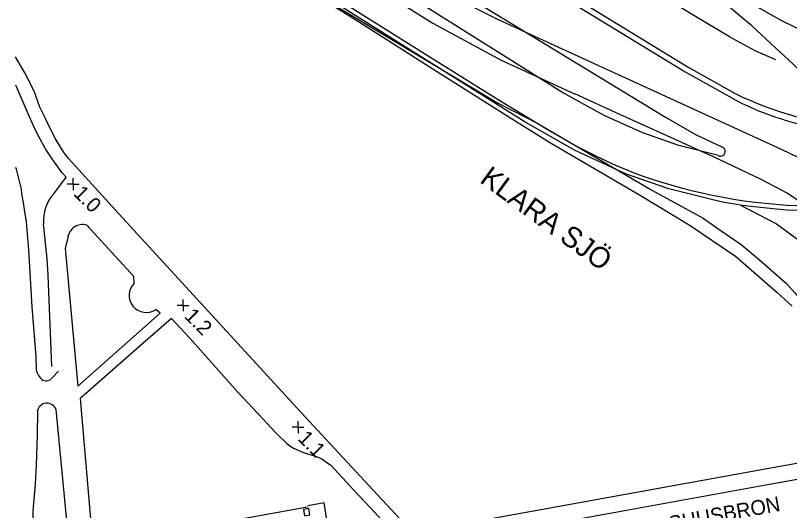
# Model space of a CAD drawing. Extents: x 1596643 to 1597288, y 13057194 to 13057957.
# Drawn here: x 1596648.4 to 1596778.7, y 13057439.2 to 13057522.5 of the extents above; entities that cross this region are included whole.
import ezdxf

# ---------------------------------------------------------------- set-up
doc = ezdxf.new("R2010")
doc.units = 0
for name, color, linetype in [('A spårmitt L', 7, 'Continuous'), ('BAS bro ej def L', 7, 'Continuous'), ('BAS fastighetsgräns samfällighet L', 7, 'Continuous'), ('BAS gång- cykelväg L', 7, 'Continuous'), ('BAS kajkant L', 7, 'Continuous'), ('BAS Level 16', 7, 'Continuous'), ('BAS Level 18', 7, 'Continuous'), ('BAS Level 19', 7, 'Continuous'), ('BAS Level 34', 7, 'Continuous'), ('BAS markytetext T', 7, 'Continuous'), ('BAS väg T', 7, 'Continuous'), ('BAS vägbanekant L', 7, 'Continuous'), ('BAS vägbanekant skymd L', 7, 'Continuous')]:
    doc.layers.add(name, color=color, linetype=linetype)

msp = doc.modelspace()

# ---------------------------------------------------------------- linework, layer by layer
at = {"layer": 'A spårmitt L'}
msp.add_arc((1597114.01, 13057796.63), 410, 212.1854, 226.2937, dxfattribs=at)
at = {"layer": 'BAS bro ej def L'}
for points in [[(1596776.38, 13057515.07), (1596772.93, 13057516.59), (1596768.6, 13057518.91), (1596762.32, 13057522.67), (1596686.06, 13057569.11), (1596672.38, 13057577.4), (1596669.04, 13057579.43), (1596663.37, 13057582.83)], [(1596675.99, 13057583.08), (1596765.97, 13057528.32), (1596771.95, 13057524.7), (1596777.33, 13057521.65), (1596783.79, 13057518.55), (1596789.25, 13057516.42), (1596794.25, 13057515.28), (1596798.61, 13057515.01), (1596803.07, 13057515.31)], [(1596766.73, 13057498.92), (1596760.08, 13057500.64), (1596754.02, 13057502.74), (1596747.52, 13057505.66), (1596740.35, 13057509.61), (1596648.37, 13057567.37)], [(1596765.57, 13057491.51), (1596758.36, 13057493.35), (1596751.1, 13057495.85), (1596742.51, 13057499.82), (1596734.05, 13057504.69), (1596648.37, 13057558.52)], [(1596670.44, 13057558.6), (1596757.81, 13057505.41), (1596763.01, 13057502.44), (1596767.29, 13057500.38)], [(1596873.3, 13057525.88), (1596855.75, 13057517.01), (1596837.58, 13057507.61), (1596820.66, 13057499.01), (1596812.84, 13057495.44), (1596806.32, 13057492.94), (1596797.79, 13057490.83), (1596791.9, 13057490.12), (1596786.01, 13057489.63), (1596782.53, 13057489.62), (1596780.07, 13057489.65), (1596778.3, 13057489.75), (1596776.53, 13057489.91), (1596771.66, 13057490.41), (1596770.47, 13057490.58)], [(1596770.47, 13057490.58), (1596768.82, 13057490.83), (1596767.72, 13057491.04), (1596765.57, 13057491.51)], [(1596701.55, 13057432.92), (1596795.38, 13057449.95), (1596800, 13057453.76)]]:
    msp.add_lwpolyline(points, dxfattribs=at)
msp.add_arc((1596767.1, 13057499.62), 0.789, 240.3812, 77.7075, dxfattribs=at)
at = {"layer": 'BAS fastighetsgräns samfällighet L'}
msp.add_lwpolyline([(1596648.37, 13057557.67), (1596669.21, 13057544.62), (1596696.73, 13057527.52), (1596729.51, 13057507.81), (1596732.16, 13057506.46), (1596736.21, 13057504.41), (1596755.64, 13057493.06), (1596764.14, 13057488.41), (1596767.22, 13057486.28), (1596770.57, 13057483.95), (1596773.67, 13057481.35), (1596776.84, 13057478.59), (1596778.22, 13057477.39), (1596779.59, 13057475.84), (1596783.22, 13057471.46), (1596786.31, 13057467.11), (1596788.64, 13057463.85), (1596790.09, 13057461.2), (1596791.17, 13057459.15)], dxfattribs=at)
at = {"layer": 'BAS gång- cykelväg L'}
for points in [[(1596654.84, 13057492.51), (1596656.89, 13057495.29), (1596656.18, 13057496.08), (1596654.54, 13057498.39), (1596653.4, 13057500.08), (1596652.26, 13057502.21), (1596651.49, 13057503.81), (1596650.5, 13057505.95), (1596648.43, 13057510.76)], [(1596648.37, 13057496.96), (1596648.47, 13057496.66), (1596648.79, 13057495.51), (1596649.01, 13057494.63), (1596649.32, 13057493.29), (1596649.41, 13057492.47), (1596649.67, 13057491.03), (1596649.84, 13057489.86), (1596650.17, 13057487.77), (1596650.55, 13057483.06), (1596651.13, 13057473.46), (1596651.78, 13057465.08), (1596651.87, 13057462.85)], [(1596654.49, 13057463.43), (1596653.9, 13057478.77), (1596653.68, 13057481.54), (1596653.1, 13057487.43)], [(1596668.37, 13057477.42), (1596668.3, 13057478.55), (1596660.37, 13057487.21)], [(1596657.17, 13057485.05), (1596656.75, 13057483.32), (1596658.88, 13057460.07)], [(1596658.88, 13057460.07), (1596672.71, 13057472.36), (1596671.98, 13057472.98)], [(1596685.78, 13057459.15), (1596677.72, 13057468.15), (1596674.62, 13057471.47), (1596669.81, 13057467.28), (1596660.57, 13057459.15)], [(1596654.59, 13057461.55), (1596655.62, 13057462.6)], [(1596660.57, 13057459.15), (1596659.29, 13057457.99), (1596661.01, 13057437.74)], [(1596685.78, 13057459.15), (1596689.24, 13057455.42), (1596692.23, 13057452.24), (1596694.09, 13057450.42), (1596694.74, 13057449.91), (1596695.2, 13057449.63), (1596696.08, 13057449.26), (1596696.88, 13057448.94), (1596698.08, 13057448.55), (1596698.88, 13057448.29), (1596699.97, 13057447.87), (1596701.53, 13057446.75), (1596705.35, 13057442.6), (1596708.96, 13057438.78), (1596712.4, 13057434.89)], [(1596657.09, 13057436.87), (1596655.2, 13057456.14)]]:
    msp.add_lwpolyline(points, dxfattribs=at)
for centre, radius, start, end in [((1596659.69, 13057488), 6.62, 137.1066, 184.924), ((1596659.7, 13057484.76), 2.55, 74.737, 173.4662), ((1596670.38, 13057475.37), 2.87, 134.4079, 303.9057), ((1596654.59, 13057463.38), 2.77, 190.9855, 234.6811), ((1596653.52, 13057462.33), 1.33, 246.1732, 323.6558), ((1596653.66, 13057455.59), 1.64, 19.44, 169.7795)]:
    msp.add_arc(centre, radius, start, end, dxfattribs=at)
at = {"layer": 'BAS kajkant L'}
for points in [[(1596648.37, 13057557.76), (1596661.05, 13057549.78), (1596672.77, 13057542.39), (1596688.02, 13057532.81), (1596705.04, 13057522.16), (1596719.86, 13057512.73), (1596731.89, 13057505.16), (1596738.44, 13057501.07), (1596745.06, 13057497.19), (1596753.44, 13057492.3), (1596761.8, 13057487.28), (1596769.62, 13057482.01), (1596776.64, 13057475.89), (1596777.87, 13057474.75), (1596779.15, 13057473.58)], [(1596693.3, 13057459.15), (1596665.79, 13057489.11), (1596657.34, 13057498.35), (1596656.59, 13057499.36), (1596656.08, 13057500.15), (1596655.1, 13057501.76), (1596654.26, 13057503.36), (1596653.39, 13057505.28), (1596652.5, 13057507.07), (1596651.76, 13057509.15), (1596651.57, 13057509.67), (1596649.93, 13057512.88), (1596648.37, 13057515.57)], [(1596715.28, 13057435.41), (1596704.96, 13057446.53), (1596696.4, 13057455.7), (1596693.3, 13057459.15)]]:
    msp.add_lwpolyline(points, dxfattribs=at)
at = {"layer": 'BAS Level 16'}
for p, q in [((1596658.08, 13057494.12), (1596658.08, 13057495.12)), ((1596658.08, 13057494.12), (1596658.08, 13057495.12)), ((1596658.08, 13057494.12), (1596657.08, 13057494.12)), ((1596658.08, 13057494.12), (1596657.08, 13057494.12)), ((1596658.08, 13057494.12), (1596659.08, 13057494.12)), ((1596658.08, 13057494.12), (1596658.08, 13057493.12)), ((1596658.08, 13057494.12), (1596659.08, 13057494.12)), ((1596658.08, 13057494.12), (1596658.08, 13057493.12)), ((1596676.58, 13057473.7), (1596675.58, 13057473.7)), ((1596676.58, 13057473.7), (1596675.58, 13057473.7)), ((1596676.58, 13057473.7), (1596676.58, 13057474.7)), ((1596676.58, 13057473.7), (1596676.58, 13057474.7)), ((1596676.58, 13057473.7), (1596677.58, 13057473.7)), ((1596676.58, 13057473.7), (1596676.58, 13057472.7)), ((1596676.58, 13057473.7), (1596677.58, 13057473.7)), ((1596676.58, 13057473.7), (1596676.58, 13057472.7)), ((1596695.95, 13057453.19), (1596695.95, 13057454.19)), ((1596695.95, 13057453.19), (1596695.95, 13057454.19)), ((1596695.95, 13057453.19), (1596694.95, 13057453.19)), ((1596695.95, 13057453.19), (1596694.95, 13057453.19)), ((1596695.95, 13057453.19), (1596696.95, 13057453.19)), ((1596695.95, 13057453.19), (1596695.95, 13057452.19)), ((1596695.95, 13057453.19), (1596696.95, 13057453.19)), ((1596695.95, 13057453.19), (1596695.95, 13057452.19))]:
    msp.add_line(p, q, dxfattribs=at)
at = {"layer": 'BAS Level 18'}
for points in [[(1596770.47, 13057490.58), (1596776.52, 13057487.43), (1596789.46, 13057477.93), (1596801.58, 13057462.26), (1596801.66, 13057460.1)], [(1596697.94, 13057438.4), (1596697.74, 13057439.5), (1596696.88, 13057439.32), (1596697.05, 13057438.25), (1596697.94, 13057438.4)]]:
    msp.add_lwpolyline(points, dxfattribs=at)
at = {"layer": 'BAS Level 19'}
msp.add_lwpolyline([(1596701.55, 13057432.92), (1596700.33, 13057440.46), (1596697.62, 13057439.96)], dxfattribs=at)
at = {"layer": 'BAS vägbanekant L'}
for points in [[(1596769.06, 13057508.57), (1596760.68, 13057513.25), (1596684.48, 13057559.78), (1596674.92, 13057565.63)], [(1596678.67, 13057564.56), (1596684.97, 13057560.66), (1596761.76, 13057513.76), (1596769.53, 13057509.38)], [(1596751.83, 13057496.28), (1596749.67, 13057497.17), (1596746.71, 13057498.52), (1596742.69, 13057500.57), (1596738.17, 13057503.13), (1596729.64, 13057508.3), (1596717.88, 13057515.66), (1596705.07, 13057523.72), (1596690.57, 13057532.89), (1596675.85, 13057542.06), (1596661.5, 13057551.14), (1596648.37, 13057559.38)], [(1596728.93, 13057522.17), (1596722.31, 13057525.53), (1596712.94, 13057531.01), (1596706.2, 13057535.12), (1596704.38, 13057536.39), (1596703.59, 13057537.21), (1596702.67, 13057538.71)], [(1596728.93, 13057522.17), (1596734.4, 13057519.67)], [(1596736.14, 13057512.25), (1596742.52, 13057509.34)], [(1596742.52, 13057509.34), (1596742.49, 13057509.37), (1596750.06, 13057505.92), (1596758.02, 13057502.3), (1596763.8, 13057499.68)], [(1596652.06, 13057455.97), (1596652.01, 13057451.81), (1596651.83, 13057446.86), (1596651.66, 13057443.61), (1596651.3, 13057439.08), (1596651.36, 13057433.62), (1596651.38, 13057432.1)], [(1596648.37, 13057423.28), (1596663.82, 13057426.1), (1596679.99, 13057429.02), (1596685.87, 13057430.02), (1596688.26, 13057430.05), (1596691.2, 13057429.7), (1596694.78, 13057429.39), (1596696.75, 13057429.34), (1596706.65, 13057431.17), (1596724.24, 13057434.34), (1596748.19, 13057438.67), (1596774.7, 13057443.5), (1596786.95, 13057445.68), (1596794.41, 13057447.06), (1596798.34, 13057447.86)], [(1596661.01, 13057437.74), (1596661.48, 13057433.31), (1596672.41, 13057435.25), (1596697.57, 13057439.77)]]:
    msp.add_lwpolyline(points, dxfattribs=at)
for centre, radius, start, end in [((1596795.48, 13057562.8), 59.39, 244.094, 286.2687), ((1596792.32, 13057552.36), 49.58, 242.0214, 257.1583), ((1596783.99, 13057581.52), 91.11, 249.3267, 267.5511)]:
    msp.add_arc(centre, radius, start, end, dxfattribs=at)
at = {"layer": 'BAS vägbanekant skymd L'}
for points in [[(1596659.15, 13057560.6), (1596660.87, 13057558.97), (1596668.03, 13057553.3), (1596675.45, 13057548.38), (1596704.36, 13057530.21), (1596718.63, 13057521.22), (1596730.14, 13057515), (1596736.14, 13057512.25)], [(1596734.4, 13057519.67), (1596777.31, 13057499.98), (1596781.71, 13057497.89), (1596786.33, 13057495.38), (1596790.07, 13057492.92), (1596792.74, 13057490.97), (1596794.32, 13057493.11), (1596789.33, 13057501.67), (1596787.63, 13057504.44), (1596785.6, 13057507.25), (1596782.43, 13057511.17), (1596779.37, 13057514.26), (1596772.33, 13057520.75), (1596767.57, 13057524.75)], [(1596763.8, 13057499.68), (1596765.73, 13057498.8), (1596773.89, 13057494.98), (1596778.37, 13057492.58), (1596782.88, 13057489.61)]]:
    msp.add_lwpolyline(points, dxfattribs=at)

# ---------------------------------------------------------------- texts
at = {"layer": 'BAS Level 34'}
msp.add_text('KLARA SJÖ', height=3.499, rotation=323.8229, dxfattribs=at).set_placement((1596726.36, 13057494.53))
at = {"layer": 'BAS markytetext T'}
for s, p in [('1.0', (1596658, 13057492.38)), ('1.2', (1596676.65, 13057471.73)), ('1.1', (1596695.77, 13057451.14))]:
    msp.add_text(s, height=2.5, rotation=315, dxfattribs=at).set_placement(p)
at = {"layer": 'BAS väg T'}
msp.add_text('STADSHUSBRON', height=2.5, rotation=10.431, dxfattribs=at).set_placement((1596749.89, 13057434.07))

doc.saveas('drawing.dxf')
